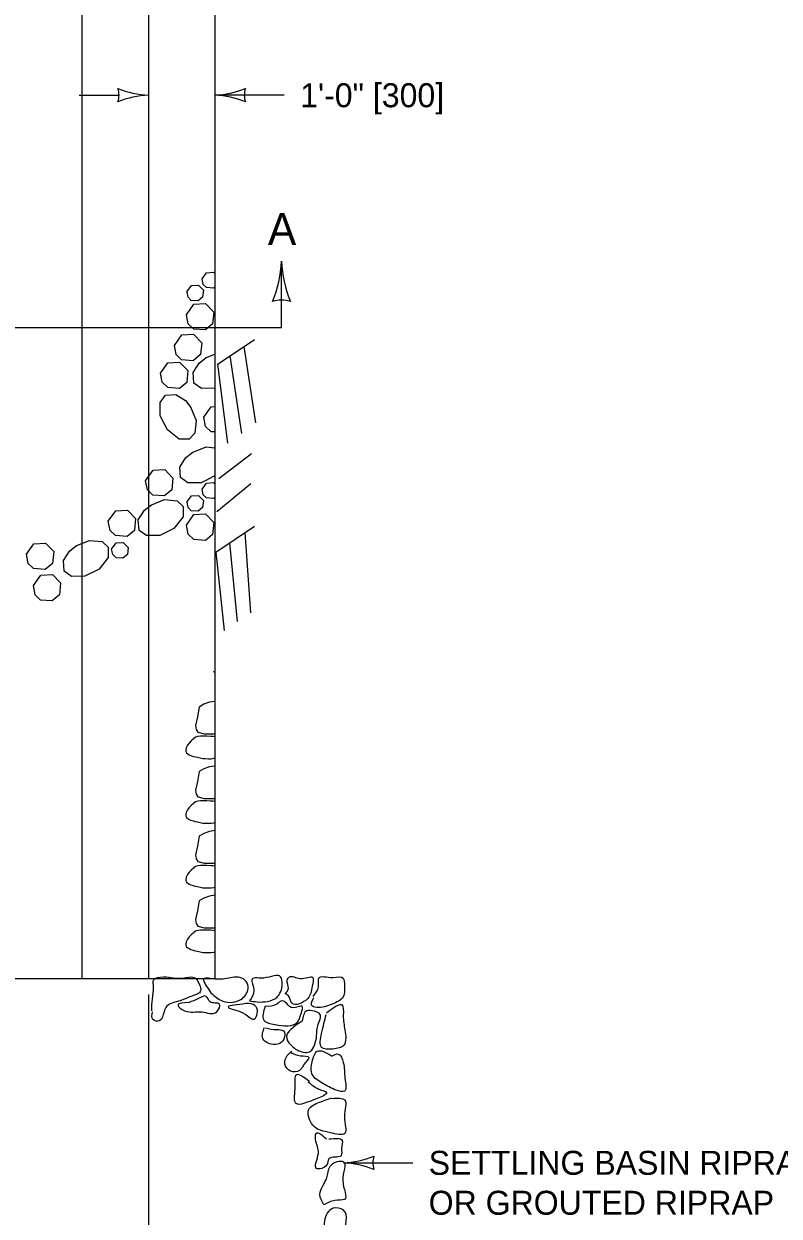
# Model space of a CAD drawing. Extents: x 49991.4 to 50021, y 49987.6 to 50011.4.
# Drawn here: x 50001.321 to 50003.212, y 49993.444 to 49996.429 of the extents above; entities that cross this region are included whole.
import ezdxf

# ---------------------------------------------------------------- set-up
doc = ezdxf.new("R2010")
doc.units = 0
for name, color, linetype in [('Level 1', 7, 'Continuous'), ('Level 2', 7, 'Continuous'), ('Level 3', 7, 'Continuous'), ('Level 6', 7, 'Continuous')]:
    doc.layers.add(name, color=color, linetype=linetype)

msp = doc.modelspace()

# ---------------------------------------------------------------- linework, layer by layer
at = {"layer": 'Level 1'}
for p, q in [((50001.4658, 49997.6503), (50001.4658, 49994.0392)), ((50001.6325, 49997.2058), (50001.6325, 49994.0392)), ((50001.7992, 49997.1915), (50001.7992, 49994.0392)), ((50001.8046, 49995.5769), (50001.8986, 49995.6394)), ((50001.8716, 49995.6214), (50001.9005, 49995.4306)), ((50001.7759, 49995.5931), (50001.7992, 49995.6023)), ((50001.8363, 49995.598), (50001.8657, 49995.4042)), ((50001.8058, 49995.5777), (50001.8311, 49995.3793)), ((50001.8094, 49995.2916), (50001.8905, 49995.3536)), ((50001.8042, 49995.2086), (50001.8889, 49995.2788)), ((50001.8017, 49995.107), (50001.898, 49995.1716)), ((50001.8745, 49995.1558), (50001.8883, 49994.9551)), ((50001.8358, 49995.1298), (50001.8546, 49994.933)), ((50001.8017, 49995.107), (50001.822, 49994.9107)), ((50000.7991, 49994.0392), (50001.7992, 49994.0392))]:
    msp.add_line(p, q, dxfattribs=at)
for points in [[(50001.7673, 49995.7908), (50001.7784, 49995.8065), (50001.796, 49995.8075), (50001.7992, 49995.8042)], [(50001.7292, 49995.7588), (50001.7403, 49995.7745), (50001.758, 49995.7755), (50001.7702, 49995.7628), (50001.7685, 49995.745), (50001.7576, 49995.7359), (50001.7401, 49995.7371), (50001.7319, 49995.7451), (50001.7293, 49995.7588)], [(50001.7992, 49995.7709), (50001.7956, 49995.7679), (50001.7782, 49995.7691), (50001.77, 49995.7771), (50001.7673, 49995.7908)], [(50001.728, 49995.7011), (50001.7465, 49995.7274), (50001.7759, 49995.7291), (50001.7964, 49995.7078), (50001.7934, 49995.6781), (50001.7752, 49995.663), (50001.7461, 49995.6651), (50001.7325, 49995.6783), (50001.728, 49995.7011)], [(50001.6978, 49995.6243), (50001.7162, 49995.6506), (50001.7456, 49995.6522), (50001.7661, 49995.631), (50001.7632, 49995.6013), (50001.745, 49995.5861), (50001.7159, 49995.5883), (50001.7022, 49995.6015), (50001.6978, 49995.6243)], [(50001.7992, 49995.5174), (50001.7985, 49995.5171), (50001.7652, 49995.5165), (50001.7465, 49995.5298), (50001.7447, 49995.5563), (50001.7599, 49995.5801), (50001.7773, 49995.594)], [(50001.6631, 49995.5549), (50001.6815, 49995.5812), (50001.7109, 49995.5828), (50001.7314, 49995.5616), (50001.7285, 49995.5319), (50001.7103, 49995.5167), (50001.6812, 49995.5189), (50001.6675, 49995.5321), (50001.6631, 49995.5549)], [(50001.7384, 49995.4706), (50001.7521, 49995.4361), (50001.7493, 49995.4044), (50001.735, 49995.3893), (50001.7093, 49995.3898), (50001.6801, 49995.4127), (50001.6624, 49995.448), (50001.6618, 49995.4813), (50001.6751, 49995.5), (50001.7017, 49995.5018), (50001.7254, 49995.4866), (50001.7393, 49995.4692)], [(50001.7715, 49995.4445), (50001.79, 49995.4707), (50001.7992, 49995.4712)], [(50001.7992, 49995.4077), (50001.7897, 49995.4084), (50001.776, 49995.4217), (50001.7715, 49995.4445)], [(50001.7992, 49995.2977), (50001.765, 49995.2806), (50001.7317, 49995.28), (50001.713, 49995.2933), (50001.7112, 49995.3198), (50001.7264, 49995.3435), (50001.7438, 49995.3574)], [(50001.7425, 49995.3566), (50001.777, 49995.3702), (50001.7992, 49995.3683)], [(50001.6258, 49995.2856), (50001.6442, 49995.3119), (50001.6737, 49995.3136), (50001.6941, 49995.2923), (50001.6912, 49995.2626), (50001.673, 49995.2475), (50001.6439, 49995.2496), (50001.6302, 49995.2628), (50001.6258, 49995.2856)], [(50001.7673, 49995.2641), (50001.7784, 49995.2799), (50001.796, 49995.2809), (50001.7992, 49995.2776)], [(50001.7992, 49995.2442), (50001.7956, 49995.2412), (50001.7782, 49995.2425), (50001.77, 49995.2504), (50001.7673, 49995.2641)], [(50001.6387, 49995.2247), (50001.6732, 49995.2383), (50001.7048, 49995.2356), (50001.7199, 49995.2213), (50001.7194, 49995.1955), (50001.6966, 49995.1663), (50001.6612, 49995.1487), (50001.6279, 49995.1481), (50001.6092, 49995.1614), (50001.6074, 49995.1879), (50001.6226, 49995.2116), (50001.6401, 49995.2255)], [(50001.7292, 49995.2321), (50001.7403, 49995.2479), (50001.758, 49995.2489), (50001.7702, 49995.2361), (50001.7685, 49995.2183), (50001.7576, 49995.2092), (50001.7401, 49995.2105), (50001.7319, 49995.2184), (50001.7293, 49995.2321)], [(50001.5323, 49995.1842), (50001.5508, 49995.2104), (50001.5802, 49995.2121), (50001.6007, 49995.1909), (50001.5977, 49995.1612), (50001.5795, 49995.146), (50001.5504, 49995.1481), (50001.5368, 49995.1614), (50001.5323, 49995.1842)], [(50001.728, 49995.1745), (50001.7465, 49995.2007), (50001.7759, 49995.2024), (50001.7964, 49995.1812), (50001.7934, 49995.1514), (50001.7752, 49995.1363), (50001.7461, 49995.1384), (50001.7325, 49995.1517), (50001.728, 49995.1745)], [(50001.3273, 49995.1016), (50001.3457, 49995.1279), (50001.3752, 49995.1296), (50001.3957, 49995.1083), (50001.3927, 49995.0786), (50001.3745, 49995.0635), (50001.3454, 49995.0656), (50001.3317, 49995.0788), (50001.3273, 49995.1016)], [(50001.451, 49995.1226), (50001.4856, 49995.1363), (50001.5172, 49995.1336), (50001.5323, 49995.1192), (50001.5318, 49995.0935), (50001.509, 49995.0643), (50001.4736, 49995.0466), (50001.4403, 49995.0461), (50001.4216, 49995.0594), (50001.4198, 49995.0859), (50001.435, 49995.1096), (50001.4524, 49995.1235)], [(50001.5407, 49995.1145), (50001.5518, 49995.1302), (50001.5694, 49995.1312), (50001.5817, 49995.1185), (50001.58, 49995.1007), (50001.569, 49995.0916), (50001.5516, 49995.0929), (50001.5434, 49995.1008), (50001.5407, 49995.1145)], [(50001.7992, 49995.0904), (50001.7977, 49995.089)], [(50001.3447, 49995.0231), (50001.3631, 49995.0493), (50001.3925, 49995.051), (50001.413, 49995.0298), (50001.41, 49995.0001), (50001.3919, 49994.9849), (50001.3628, 49994.987), (50001.3491, 49995.0003), (50001.3447, 49995.0231)], [(50001.7992, 49994.806), (50001.7952, 49994.8071), (50001.7949, 49994.8071)], [(50001.7992, 49994.7332), (50001.7857, 49994.731), (50001.7714, 49994.7261), (50001.76, 49994.7191), (50001.7552, 49994.6947), (50001.7507, 49994.6728), (50001.7522, 49994.6625), (50001.7566, 49994.6557), (50001.7724, 49994.6522), (50001.7992, 49994.6522)], [(50001.7992, 49994.6442), (50001.7952, 49994.6453), (50001.788, 49994.6455), (50001.7789, 49994.6457), (50001.7698, 49994.6457), (50001.7629, 49994.6457), (50001.7565, 49994.645), (50001.7509, 49994.6433), (50001.7457, 49994.6394), (50001.7398, 49994.6345), (50001.7349, 49994.6289), (50001.7309, 49994.6233), (50001.7272, 49994.6166), (50001.7265, 49994.6112), (50001.7265, 49994.6074), (50001.728, 49994.6045), (50001.7312, 49994.6021), (50001.7346, 49994.5996), (50001.7393, 49994.5978), (50001.7447, 49994.5956), (50001.7501, 49994.5942), (50001.7555, 49994.5933), (50001.7619, 49994.5915), (50001.7691, 49994.5902), (50001.775, 49994.5902), (50001.7834, 49994.5897), (50001.7895, 49994.5897), (50001.7962, 49994.5906), (50001.7992, 49994.5919)], [(50001.7992, 49994.5713), (50001.7857, 49994.5691), (50001.7714, 49994.5642), (50001.76, 49994.5573), (50001.7552, 49994.5329), (50001.7507, 49994.5109), (50001.7522, 49994.5006), (50001.7566, 49994.4939), (50001.7724, 49994.4903), (50001.7992, 49994.4903)], [(50001.7992, 49994.4824), (50001.7952, 49994.4834), (50001.788, 49994.4837), (50001.7789, 49994.4839), (50001.7698, 49994.4839), (50001.7629, 49994.4839), (50001.7565, 49994.4832), (50001.7509, 49994.4814), (50001.7457, 49994.4776), (50001.7398, 49994.4727), (50001.7349, 49994.4671), (50001.7309, 49994.4615), (50001.7272, 49994.4548), (50001.7265, 49994.4494), (50001.7265, 49994.4456), (50001.728, 49994.4427), (50001.7312, 49994.4402), (50001.7346, 49994.4378), (50001.7393, 49994.436), (50001.7447, 49994.4337), (50001.7501, 49994.4324), (50001.7555, 49994.4315), (50001.7619, 49994.4297), (50001.7691, 49994.4284), (50001.775, 49994.4284), (50001.7834, 49994.4279), (50001.7895, 49994.4279), (50001.7962, 49994.4288), (50001.7992, 49994.4301)], [(50001.7992, 49994.4095), (50001.7857, 49994.4073), (50001.7714, 49994.4024), (50001.76, 49994.3954), (50001.7552, 49994.371), (50001.7507, 49994.3491), (50001.7522, 49994.3388), (50001.7566, 49994.3321), (50001.7724, 49994.3285), (50001.7992, 49994.3285)], [(50001.7992, 49994.3205), (50001.7952, 49994.3216), (50001.788, 49994.3218), (50001.7789, 49994.322), (50001.7698, 49994.322), (50001.7629, 49994.322), (50001.7565, 49994.3214), (50001.7509, 49994.3196), (50001.7457, 49994.3158), (50001.7398, 49994.3108), (50001.7349, 49994.3052), (50001.7309, 49994.2997), (50001.7272, 49994.2929), (50001.7265, 49994.2876), (50001.7265, 49994.2838), (50001.728, 49994.2808), (50001.7312, 49994.2784), (50001.7346, 49994.2759), (50001.7393, 49994.2741), (50001.7447, 49994.2719), (50001.7501, 49994.2705), (50001.7555, 49994.2696), (50001.7619, 49994.2679), (50001.7691, 49994.2665), (50001.775, 49994.2665), (50001.7834, 49994.2661), (50001.7895, 49994.2661), (50001.7962, 49994.267), (50001.7992, 49994.2682)], [(50001.7992, 49994.2476), (50001.7857, 49994.2455), (50001.7714, 49994.2405), (50001.76, 49994.2336), (50001.7552, 49994.2092), (50001.7507, 49994.1873), (50001.7522, 49994.177), (50001.7566, 49994.1702), (50001.7724, 49994.1666), (50001.7992, 49994.1666)], [(50001.7992, 49994.1587), (50001.7952, 49994.1598), (50001.788, 49994.16), (50001.7789, 49994.1602), (50001.7698, 49994.1602), (50001.7629, 49994.1602), (50001.7565, 49994.1595), (50001.7509, 49994.1577), (50001.7457, 49994.1539), (50001.7398, 49994.149), (50001.7349, 49994.1434), (50001.7309, 49994.1378), (50001.7272, 49994.1311), (50001.7265, 49994.1257), (50001.7265, 49994.1219), (50001.728, 49994.119), (50001.7312, 49994.1165), (50001.7346, 49994.1141), (50001.7393, 49994.1123), (50001.7447, 49994.11), (50001.7501, 49994.1087), (50001.7555, 49994.1078), (50001.7619, 49994.106), (50001.7691, 49994.1047), (50001.775, 49994.1047), (50001.7834, 49994.1042), (50001.7895, 49994.1042), (50001.7962, 49994.1051), (50001.7992, 49994.1064)]]:
    msp.add_lwpolyline(points, dxfattribs=at)
for points in [[(50001.6413, 49993.9586), (50001.6427, 49993.9878), (50001.6455, 49994.0198), (50001.6455, 49994.035), (50001.6705, 49994.0434), (50001.7191, 49994.0406), (50001.7469, 49994.042), (50001.7608, 49994.0239), (50001.7635, 49994.0086), (50001.7399, 49993.9947), (50001.7121, 49993.9836), (50001.6788, 49993.9697), (50001.6718, 49993.9559), (50001.6607, 49993.9336), (50001.6441, 49993.9364), (50001.6427, 49993.9559)], [(50001.7871, 49994.0059), (50001.776, 49994.0239), (50001.7705, 49994.0378), (50001.7885, 49994.0392), (50001.8288, 49994.0392), (50001.8663, 49994.0406), (50001.8802, 49994.0281), (50001.8816, 49994.01), (50001.8608, 49993.985), (50001.8136, 49993.985), (50001.7871, 49994.0059)], [(50001.8858, 49993.9836), (50001.8969, 49994.0086), (50001.8927, 49994.0378), (50001.9219, 49994.0406), (50001.9636, 49994.0434), (50001.9677, 49994.0253), (50001.9539, 49993.992), (50001.9052, 49993.9809), (50001.8858, 49993.9836)], [(50001.9747, 49994.0003), (50001.983, 49994.0142), (50001.9803, 49994.035), (50001.9858, 49994.0434), (50002.0122, 49994.0392), (50002.0441, 49994.042), (50002.0428, 49994.0198), (50002.0316, 49993.9892), (50001.9914, 49993.9781), (50001.983, 49993.9961), (50001.9747, 49994.0017)], [(50002.0455, 49993.9947), (50002.0581, 49994.0184), (50002.0594, 49994.0406), (50002.0942, 49994.042), (50002.1206, 49994.0406), (50002.1233, 49994.0212), (50002.1206, 49993.9934), (50002.0928, 49993.9753), (50002.0733, 49993.9684), (50002.0414, 49993.9725), (50002.0469, 49993.992)], [(50001.7344, 49993.9795), (50001.758, 49993.9892), (50001.7774, 49993.9947), (50001.7871, 49993.9809), (50001.8108, 49993.9753), (50001.8038, 49993.9559), (50001.7663, 49993.9559), (50001.7233, 49993.9586), (50001.7066, 49993.9725), (50001.7344, 49993.9795)], [(50001.8691, 49993.9753), (50001.8844, 49993.9767), (50001.9025, 49993.9684), (50001.9052, 49993.9517), (50001.8983, 49993.9378), (50001.8747, 49993.9503), (50001.8511, 49993.96), (50001.833, 49993.967), (50001.8691, 49993.9753)], [(50001.9247, 49993.9697), (50001.9539, 49993.9753), (50001.9677, 49993.9836), (50001.9789, 49993.9767), (50001.9941, 49993.9656), (50002.0178, 49993.9697), (50002.015, 49993.9517), (50002.0053, 49993.9295), (50001.9497, 49993.9239), (50001.9219, 49993.935), (50001.9247, 49993.9697)], [(50002.0789, 49993.9531), (50002.0969, 49993.967), (50002.1164, 49993.9739), (50002.1206, 49993.9475), (50002.1247, 49993.91), (50002.1219, 49993.8725), (50002.0942, 49993.8628), (50002.0664, 49993.867), (50002.0664, 49993.9017), (50002.0775, 49993.9489)], [(50002.0178, 49993.9322), (50002.0289, 49993.9586), (50002.0483, 49993.9572), (50002.0622, 49993.9503), (50002.0567, 49993.9211), (50002.0539, 49993.8961), (50002.0483, 49993.8725), (50002.0386, 49993.8572), (50002.0094, 49993.8586), (50001.9941, 49993.8683), (50001.9789, 49993.8892), (50002.0178, 49993.9322)], [(50001.9261, 49993.9156), (50001.9552, 49993.9114), (50001.9705, 49993.9086), (50001.9719, 49993.8878), (50001.9566, 49993.8753), (50001.9191, 49993.8892), (50001.9233, 49993.917)], [(50001.9886, 49993.8545), (50002.0136, 49993.8461), (50002.0344, 49993.8419), (50002.0219, 49993.8239), (50002.015, 49993.8128), (50001.9941, 49993.8058), (50001.9761, 49993.8197), (50001.9775, 49993.8419), (50001.9914, 49993.8572)], [(50002.0914, 49993.8447), (50002.1081, 49993.8503), (50002.1206, 49993.8294), (50002.1247, 49993.7892), (50002.1233, 49993.7572), (50002.1025, 49993.76), (50002.0692, 49993.7767), (50002.0428, 49993.7989), (50002.0428, 49993.8308), (50002.0553, 49993.8572), (50002.0914, 49993.8461)], [(50002.033, 49993.7808), (50002.0594, 49993.7627), (50002.0789, 49993.753), (50002.0553, 49993.7391), (50002.0303, 49993.7294), (50002.0039, 49993.7252), (50001.9997, 49993.7627), (50002.0039, 49993.7989), (50002.0358, 49993.7822)], [(50002.0914, 49993.7391), (50002.1247, 49993.735), (50002.1233, 49993.6933), (50002.1247, 49993.6516), (50002.0886, 49993.653), (50002.0441, 49993.6724), (50002.0344, 49993.7114), (50002.0608, 49993.7294), (50002.0914, 49993.7405)], [(50002.0844, 49993.6377), (50002.1178, 49993.6336), (50002.1164, 49993.6141), (50002.115, 49993.596), (50002.0844, 49993.5877), (50002.0789, 49993.5724), (50002.0539, 49993.5641), (50002.0581, 49993.6016), (50002.0511, 49993.6363), (50002.0525, 49993.6516), (50002.0789, 49993.6377)], [(50002.0719, 49993.4724), (50002.0997, 49993.4835), (50002.1233, 49993.4863), (50002.1192, 49993.5335), (50002.1206, 49993.5808), (50002.09, 49993.5724), (50002.0803, 49993.5433), (50002.0622, 49993.4988), (50002.0719, 49993.4724)], [(50002.0747, 49993.3015), (50002.0956, 49993.3043), (50002.1136, 49993.3057), (50002.1289, 49993.3321), (50002.1233, 49993.396), (50002.1206, 49993.4599), (50002.0956, 49993.4641), (50002.0733, 49993.4321), (50002.0789, 49993.3904), (50002.0831, 49993.3529), (50002.0775, 49993.2988)]]:
    msp.add_spline(points, degree=3, dxfattribs=at)
at = {"layer": 'Level 3'}
for p, q in [((50001.4591, 49996.2507), (50001.5591, 49996.2507)), ((50001.9726, 49996.2507), (50001.7992, 49996.2507)), ((50001.6325, 49993.9992), (50001.6325, 49992.8309)), ((50002.1209, 49993.5779), (50002.2943, 49993.5779))]:
    msp.add_line(p, q, dxfattribs=at)
for centre, radius, start, end in [((50001.6417, 49996.4729), 0.2223, 247.456, 267.6395), ((50001.5043, 49996.2507), 0.0548, 342.1388, 17.8612), ((50001.644, 49996.018), 0.233, 92.8273, 112.0772), ((50001.7901, 49996.4729), 0.2223, 272.3605, 292.544), ((50001.7878, 49996.018), 0.233, 67.9228, 87.1727), ((50001.9275, 49996.2507), 0.0548, 162.1388, 197.8612), ((50002.1094, 49993.8106), 0.233, 272.8273, 292.0772), ((50002.2492, 49993.5779), 0.0548, 162.1388, 197.8612), ((50002.1118, 49993.3558), 0.2223, 67.456, 87.6395)]:
    msp.add_arc(centre, radius, start, end, dxfattribs=at)
at = {"layer": 'Level 6'}
for p, q in [((50001.9659, 49995.669), (50001.9659, 49995.8357)), ((50000.6323, 49995.669), (50001.9659, 49995.669))]:
    msp.add_line(p, q, dxfattribs=at)
for centre, radius, start, end in [((50001.6698, 49995.8479), 0.2964, 337.456, 357.6395), ((50002.2762, 49995.851), 0.3107, 182.8273, 202.0772), ((50001.9659, 49995.6648), 0.073, 72.1388, 107.8612)]:
    msp.add_arc(centre, radius, start, end, dxfattribs=at)

# ---------------------------------------------------------------- texts
at = {"layer": 'Level 2'}
for s, height, p in [('1\'-0" [300]', 0.06, (50002.0126, 49996.2207)), ('A', 0.08, (50001.9316, 49995.8757)), ('SETTLING BASIN RIPRAP', 0.06, (50002.3343, 49993.5479)), ('OR GROUTED RIPRAP', 0.06, (50002.3343, 49993.4479))]:
    msp.add_text(s, height=height, dxfattribs=at).set_placement(p)

doc.saveas('drawing.dxf')
